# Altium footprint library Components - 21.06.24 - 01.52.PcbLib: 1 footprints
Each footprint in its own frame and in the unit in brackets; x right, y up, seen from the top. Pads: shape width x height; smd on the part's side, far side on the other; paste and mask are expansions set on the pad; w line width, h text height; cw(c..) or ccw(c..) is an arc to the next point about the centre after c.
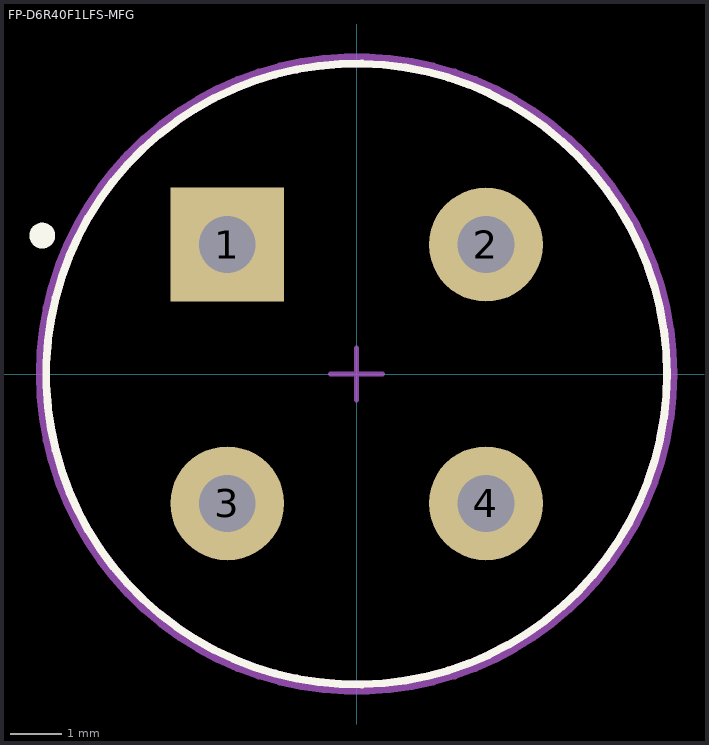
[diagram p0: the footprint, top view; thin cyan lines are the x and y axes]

## FP-D6R40F1LFS-MFG [mm]
pads (4):
  rect 2.2x2.2 hole 1.1 paste-2539.97 mask+0: 1(-2.5,2.5)
  round 2.2 hole 1.1 paste-2539.97 mask+0: 2(2.5,2.5) 3(-2.5,-2.5) 4(2.5,-2.5)
Top Overlay:
  circle w0.25: c-6.075,2.675 r0.125
  circle w0.15: c0,0 r6
Top Assembly:
  text ".Designator" at 0,0.188 h1
Top 3D Body:
  circle w0.15: c0,0 r6
Top Courtyard:
  lines w0.2: -6.1,0 ccw(c0,0) 6.1,0 ccw(c0,0) -6.1,0
Top Component Center:
  lines w0.1: -0.5,0 0.5,0 ; 0,-0.5 0,0.5
3D body "Switch_C&K_Components_D6R40F1LFS_eec.STEP": height 0.25, standoff 0, extent -6.1,-6.1 6.1,6.1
